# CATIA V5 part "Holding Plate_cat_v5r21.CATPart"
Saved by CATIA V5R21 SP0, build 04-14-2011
Part number: Holding Plate
Bounding box of the stored display mesh (mm): x -16 to 16, y -16 to 16, z 0 to 7
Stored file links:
  D:\CATIA V5R21 E-RESOURCES\CATIA-V5R21\catia-v5r21-Tut\c13-catia-v5r21-tut\c13-catia-v5r21-tut02\Bench Vice\Holding Plate_cat_v5r21.CATPart
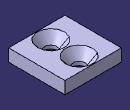
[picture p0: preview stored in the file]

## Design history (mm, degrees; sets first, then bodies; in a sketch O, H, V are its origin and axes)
Body1 (main body)
  Sketch1 on xy-plane, origin (0, 0, 0), H (1, 0, 0), V (0, 1, 0)
    line L1 (-16, 16) -> (16, 16)
    line L2 (16, 16) -> (16, -16)
    line L3 (16, -16) -> (-16, -16)
    line L4 (-16, -16) -> (-16, 16)
    construction line L5 (-16, 16) -> (16, -16)
    length L2 = 32
    length L3 = 32
    distance H L3 = 16
    distance V L4 = 16
    horizontal: L1 H, L3 H
    vertical: L2 V, L4 V
  Pad1: profile Sketch1, direction (0, 0, 1), length 7
  Sketch2 on face of Pad1, origin (-0.9262, 8.6399, 7), H (1, 0, 0), V (0, 1, 0)
    point P1 (0.9262, -0.6399)
    reference intersected line E1 through (0.9262, 0) direction (0, 1) from yz-plane
    reference projected line E3 (-15.0738, 7.3601) -> (16.9262, 7.3601) from edge of Pad1
    distance P1 E3 = 8
    coincidence: E1 P1
  Hole1: placed by Sketch2, at (0, 8, 7) direction (0, 0, -1), diameter 7, depth 10, countersink depth 5, countersink angle 80
  Mirror1: of Hole1, about zx-plane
